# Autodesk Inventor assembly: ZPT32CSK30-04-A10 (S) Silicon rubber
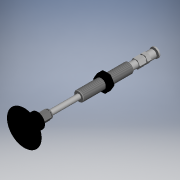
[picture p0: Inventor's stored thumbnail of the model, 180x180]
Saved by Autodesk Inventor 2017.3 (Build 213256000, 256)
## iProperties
Category: PARTsolutions
Company: SMC
Part Number: ZPT32CSK30-04-A10 (S) Silicon rubber
Catalog Web Link: www.cadenas.de
Description: ZPT-Pad Diameter Dia 20-32
Vendor: SMC
Document SubType Name: Assembly
Designer: partserver
Manufacturer: SMC
Mass: 9.11327 g
Surface Area: 77.6499 cm^2
Volume: 9.11327 cm^3
Density: 1 g/cm^3
Title: ZPT32CSK30-04-A10
Author: Cadenas PARTsolutions
Comments: Pad Diameter Dia 20-32
PSOL_IDENT_0: {$CADENAS_DATA\23d-libs\smc_jp\vacuum_equipment\vacuum_pad\zp\zpt_b\zpt_20_32_b_asmtab.prj},217 {VTY
PSOL_IDENT_1: P=3D},{STYP=ASSTAB},{NB=ZPT32CSK30-04-A10},{LINA=ZPT32CSK30-04-A10},{NN=ZPT},{DATE=12.02.2021 09:21:
PSOL_IDENT_2: 58},{GEOMDATE=29.10.2020 08:50:08},{VERSION=},{LINEID=130},{WBVAR=MATERIAL,TYPE,STROKE,PORT},{WBNUME
PSOL_IDENT_3: RIC=STROKE}  {NB=ZPT32CSK30-04-A10},{LINA=ZPT32CSK30-04-A10},{KT=DUMMY},{DIAMETER=32},{PAD=(C) Flat
PSOL_IDENT_4: with ribs},{PADX=C},{MATERIAL=S},{TYPE=K},{STROKE=30},{PORT=04},{MOUNT=(A10) M10x1 (Male thread)},{O
PSOL_IDENT_5: RDER=ZPT32CSK30-04-A10},{TIF=C2},{PPATH=zpt_20_32_b/assembly/zpt_20_32_b_asmsbl.prj},{MODEL=ZPT32CSK
PSOL_IDENT_6: 30-04-A10},{NENN=ZPT32C}
NB: ZPT32CSK30-04-A10
NN: ZPT
NT: Pad Diameter Dia 20-32
NBSYN: $ORDER.
LINA: ZPT32CSK30-04-A10
CATALOG: SMC (JP
DIAMETER: 32
PAD: (C) Flat with ribs
MATERIAL: (S) Silicon rubber
TYPE: (K) Non-rotating
STROKE: 30
PORT: (04) dia 4 tube (One-touch fitting)
MOUNT: (A10) M10x1 (Male thread)
SUPPLIER: SMC
ARTICLENO: ZPT32CSK30-04-A10
BOMINFO: ZPT32CSK30-04-A10
CREATOR: CADENAS GmbH
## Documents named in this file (5)
- e:\temp\worker_8\temp\exporttempdir_5064_318_hbBuY\format_0\ZPT32CSK30-04-A10_(S) Silicon rubber.iam
- e:\temp\worker_8\temp\exporttempdir_5064_318_hbBuY\format_0\ZP32C_T_B.ipt
- e:\temp\worker_8\temp\exporttempdir_5064_318_hbBuY\format_0\ZPT20_32_B_ADAPTER.ipt
- e:\temp\worker_8\temp\exporttempdir_5064_318_hbBuY\format_0\ZPT32C30-04-A10_B_BUFFER.ipt
- e:\temp\worker_8\temp\exporttempdir_5064_318_hbBuY\format_0\ZPT20_32_B_NUT.ipt
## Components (5 placed, 4 different names)
1. ZP32C_T_B:1
2. ZPT20_32_B_ADAPTER:1
3. ZPT32C30-04-A10_B_BUFFER:1
4. ZPT20_32_B_NUT:1
5. ZPT20_32_B_NUT:2
